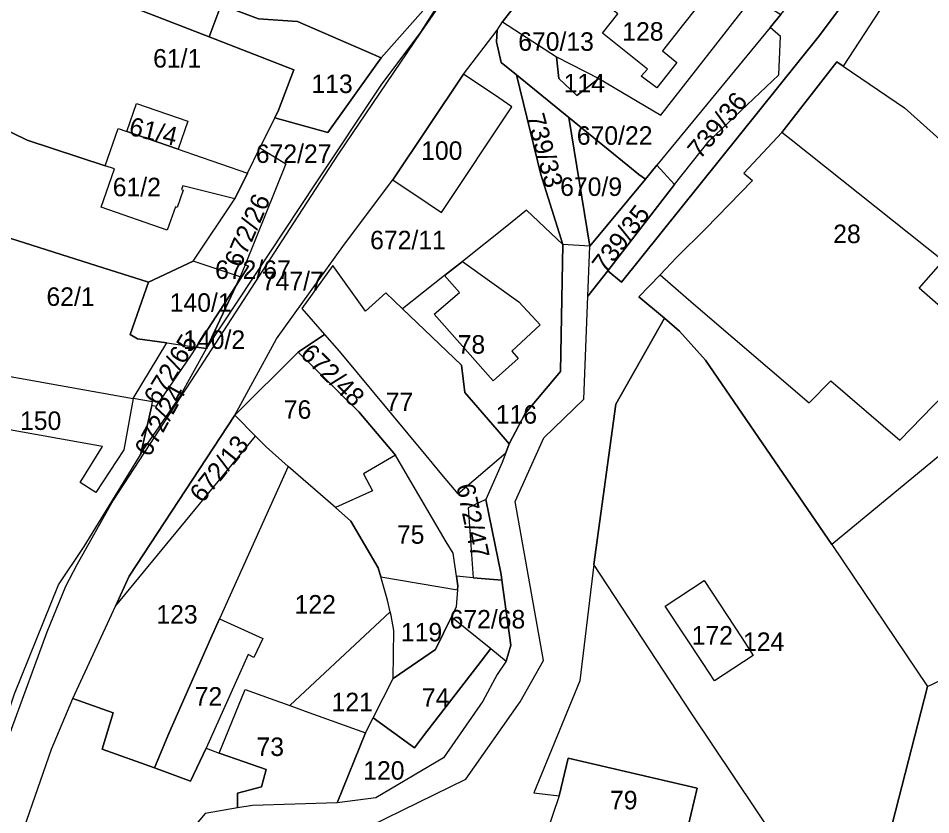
# Model space of a CAD drawing. Extents: x -629983 to -626385, y -1072828 to -1067897.
# Drawn here: x -627674 to -627526.1, y -1070665.2 to -1070536 of the extents above; entities that cross this region are included whole.
import ezdxf

# ---------------------------------------------------------------- set-up
doc = ezdxf.new("R2010")
doc.units = 0
doc.layers.add('Parcela nároku', color=7, linetype='Continuous')
doc.layers.add('Parcelní číslo', color=7, linetype='Continuous')

msp = doc.modelspace()

# ---------------------------------------------------------------- linework, layer by layer
at = {"layer": 'Parcela nároku'}
for points in [[(-627673.05, -1070667.34), (-627668.64, -1070654.56), (-627665.13, -1070646.37), (-627658.25, -1070631.4), (-627656.03, -1070626.54), (-627638.9, -1070600.43), (-627632.14, -1070588.03), (-627621.09, -1070572.65), (-627613.29, -1070562.25), (-627601.8, -1070545.09), (-627596.37, -1070537.95), (-627595.51, -1070536.64), (-627592.06, -1070532.18), (-627582.07, -1070517.94), (-627580.74, -1070516.18), (-627560.93, -1070497.47), (-627556.12, -1070493.99), (-627551.42, -1070491.21), (-627543.28, -1070485.96), (-627536.7, -1070481.88), (-627526.35, -1070474.99), (-627505.98, -1070464.68), (-627477.81, -1070449.31)], [(-627616.87, -1070667.02), (-627601.41, -1070659.46), (-627592.65, -1070646.92), (-627588.86, -1070640.21), (-627593.43, -1070614.39), (-627588.8, -1070604.09), (-627582.29, -1070597.82), (-627581.64, -1070581.12), (-627578.43, -1070576.98), (-627576.18, -1070578.86), (-627544.29, -1070539.1), (-627534.71, -1070526.26), (-627519.29, -1070510.38), (-627512.24, -1070505.66), (-627505.99, -1070502.74), (-627490.53, -1070498.43), (-627456.03, -1070492.74), (-627451.19, -1070491.95), (-627447.63, -1070491.37), (-627439.53, -1070490.04), (-627424.62, -1070486.69), (-627414.27, -1070478.04), (-627406.21, -1070468.57), (-627399.6, -1070453.47)], [(-627679.55, -1070528.79), (-627671.18, -1070532.92), (-627668.95, -1070530.68), (-627662.07, -1070534.21), (-627661.2, -1070531.98), (-627643.07, -1070539.03), (-627641.12, -1070533.86), (-627635.06, -1070536.12), (-627628.71, -1070536.58), (-627615.15, -1070542.47), (-627607.12, -1070533.38), (-627637.14, -1070522.87), (-627638.08, -1070527.06), (-627646.29, -1070525.29), (-627642.21, -1070504.86), (-627633.99, -1070506.92), (-627628.57, -1070508.55), (-627628.09, -1070506.86), (-627606.3, -1070513.99), (-627606.23, -1070513.77), (-627610.81, -1070511.8), (-627641.48, -1070502.11), (-627669.39, -1070497.42), (-627689.21, -1070528.16)], [(-627519.29, -1070510.38), (-627534.71, -1070526.26), (-627544.29, -1070539.1), (-627576.18, -1070578.86), (-627578.43, -1070576.98), (-627567.59, -1070562.99), (-627561.97, -1070555.94), (-627550.68, -1070545.19), (-627550.44, -1070538.98), (-627552.11, -1070537.56), (-627550.37, -1070535.44), (-627538.72, -1070521.1), (-627534.79, -1070517.05), (-627530.21, -1070512.83), (-627528.88, -1070511.61), (-627521.61, -1070505.05)], [(-627521.12, -1070517.11), (-627527.39, -1070524.31), (-627529.07, -1070526.23), (-627532.54, -1070531.92), (-627540.27, -1070543.83), (-627541.26, -1070543.12), (-627550.19, -1070554.58), (-627556.38, -1070561.14), (-627554.98, -1070562.37), (-627562.6, -1070570.16), (-627567.25, -1070574.84), (-627569.95, -1070577.66), (-627573.36, -1070581.22), (-627569.24, -1070584.65), (-627577.13, -1070598.62), (-627580.7, -1070624.63), (-627582.95, -1070643.48), (-627590.39, -1070661.64), (-627586.3, -1070662.14), (-627589.48, -1070671.55)], [(-627602.41, -1070529.11), (-627608.75, -1070538.3), (-627622.12, -1070558.08), (-627628.65, -1070568.14), (-627645.23, -1070593.66), (-627658.6, -1070614.18), (-627664.52, -1070624.66), (-627666.36, -1070628.21), (-627669.39, -1070635.62), (-627675.15, -1070651.38)], [(-627689.42, -1070689.81), (-627681.09, -1070664.8), (-627674.6, -1070645.58), (-627667.48, -1070627.92), (-627663.32, -1070621.69), (-627654.2, -1070606.83), (-627653.79, -1070606.16), (-627647.92, -1070597.59), (-627643.48, -1070589.58), (-627625.71, -1070562.74), (-627615.15, -1070546.88), (-627608.75, -1070538.3), (-627622.12, -1070558.08), (-627628.65, -1070568.14), (-627645.23, -1070593.66), (-627658.6, -1070614.18), (-627664.52, -1070624.66), (-627666.36, -1070628.21), (-627669.39, -1070635.62), (-627675.15, -1070651.38), (-627682.5, -1070674.74)], [(-627677.62, -1070571.01), (-627661.28, -1070576.19), (-627652.89, -1070578.85), (-627645.66, -1070575.41), (-627638.87, -1070565.34), (-627647.34, -1070563.2), (-627647.54, -1070563.8), (-627647.26, -1070563.9), (-627648.25, -1070566.73), (-627648.53, -1070566.63), (-627649.85, -1070570.41), (-627660.57, -1070566.67), (-627658.41, -1070560.48), (-627659.9, -1070559.99), (-627672.57, -1070555.81), (-627688.24, -1070548.18)], [(-627616.87, -1070667.02), (-627601.41, -1070659.46), (-627592.65, -1070646.92), (-627588.86, -1070640.21), (-627593.43, -1070614.39), (-627588.8, -1070604.09), (-627582.29, -1070597.82), (-627581.64, -1070581.12), (-627581.32, -1070573.01), (-627585.71, -1070572.7), (-627586.07, -1070593.35), (-627591.79, -1070600.14), (-627594.42, -1070605.04), (-627594.95, -1070606.49), (-627595.52, -1070608.06), (-627598.18, -1070614.09), (-627595.73, -1070626.23), (-627595.61, -1070627.14), (-627594.16, -1070637.72), (-627594.88, -1070640.29), (-627596.38, -1070642.48), (-627598.68, -1070646.78), (-627605.04, -1070655.97), (-627616.01, -1070662.49), (-627622.27, -1070663.25), (-627636.05, -1070663.69), (-627638.48, -1070664.1), (-627643.72, -1070664.99), (-627648.34, -1070670.51)], [(-627674.6, -1070645.58), (-627667.48, -1070627.92), (-627663.32, -1070621.69), (-627654.2, -1070606.83), (-627652.35, -1070598.82), (-627652.22, -1070598.24), (-627655.37, -1070597.68), (-627656.91, -1070606.05), (-627661.42, -1070612.95), (-627663.99, -1070611.33), (-627660.34, -1070605.48), (-627686.35, -1070600.86)]]:
    msp.add_lwpolyline(points, dxfattribs=at)
for points in [[(-627582.48, -1070503.53), (-627583.3, -1070504.47), (-627588.97, -1070511.44), (-627594.85, -1070518.68), (-627597.34, -1070521.75), (-627600.84, -1070525.92), (-627608.75, -1070538.3), (-627602.41, -1070529.11), (-627600.54, -1070526.75), (-627595.56, -1070520.84), (-627589.61, -1070514.26), (-627579.3, -1070504.8), (-627573.94, -1070500.28), (-627564.06, -1070492.76), (-627563.7, -1070492.26), (-627563.62, -1070491.72), (-627563.73, -1070491.09), (-627564.55, -1070487.72), (-627564.9, -1070486.29), (-627576.54, -1070496.78), (-627581.18, -1070502.06)], [(-627550.19, -1070554.58), (-627541.26, -1070543.12), (-627540.27, -1070543.83), (-627530.29, -1070550.54), (-627520.48, -1070559.4), (-627512.61, -1070563.45), (-627505.35, -1070549.36), (-627513.22, -1070545.31), (-627508.58, -1070536.93), (-627513.85, -1070533.39), (-627521.11, -1070528.52), (-627527.39, -1070524.31), (-627521.12, -1070517.11), (-627505.54, -1070534.77), (-627482.52, -1070560.73), (-627475.03, -1070556.53), (-627473.88, -1070560.2), (-627493.09, -1070564.88), (-627514.26, -1070577.27), (-627521.4, -1070577.52), (-627524.03, -1070575.35), (-627548.69, -1070555.77)], [(-627568.16, -1070523.81), (-627569.5, -1070523.01), (-627571.43, -1070523.34), (-627574.6, -1070524.75), (-627581.08, -1070528.36), (-627592.06, -1070532.18), (-627595.51, -1070536.64), (-627586.72, -1070542.29), (-627579.86, -1070545.8), (-627569.82, -1070551.77), (-627554.9, -1070532.59), (-627564.16, -1070526.72)], [(-627529.07, -1070526.23), (-627532.54, -1070531.92), (-627540.27, -1070543.83), (-627530.29, -1070550.54), (-627520.48, -1070559.4), (-627512.61, -1070563.45), (-627505.35, -1070549.36), (-627513.22, -1070545.31), (-627508.58, -1070536.93), (-627513.85, -1070533.39), (-627521.11, -1070528.52), (-627527.39, -1070524.31)], [(-627623.79, -1070554.58), (-627632.41, -1070552.2), (-627634.81, -1070557.07), (-627630.61, -1070559.65), (-627637.23, -1070576.04), (-627636.69, -1070576.22), (-627637.63, -1070577.77), (-627638.66, -1070579.37), (-627643.48, -1070589.58), (-627625.71, -1070562.74), (-627615.15, -1070546.88), (-627608.75, -1070538.3), (-627600.84, -1070525.92), (-627607.12, -1070533.38), (-627615.15, -1070542.47)], [(-627679.55, -1070528.79), (-627688.24, -1070548.18), (-627672.57, -1070555.81), (-627659.9, -1070559.99), (-627657.81, -1070553.92), (-627656.38, -1070554.41), (-627654.85, -1070549.86), (-627646.49, -1070552.75), (-627648.05, -1070557.27), (-627645.57, -1070558.14), (-627636.82, -1070561.16), (-627634.81, -1070557.07), (-627632.41, -1070552.2), (-627631.8, -1070550.95), (-627629.3, -1070544.38), (-627643.07, -1070539.03), (-627661.2, -1070531.98), (-627662.07, -1070534.21), (-627668.95, -1070530.68), (-627671.18, -1070532.92)], [(-627575.98, -1070532.62), (-627574.27, -1070530.47), (-627573.41, -1070531.16), (-627571.3, -1070528.5), (-627564.02, -1070534.33), (-627566.12, -1070536.99), (-627569.55, -1070541.31), (-627567.24, -1070543.2), (-627570.47, -1070547.33), (-627572.98, -1070545.4), (-627571.98, -1070544.27), (-627579.28, -1070538.47), (-627576.8, -1070535.34), (-627578.17, -1070534.26), (-627576.52, -1070532.19)], [(-627570.47, -1070547.33), (-627572.98, -1070545.4), (-627571.98, -1070544.27), (-627579.28, -1070538.47), (-627576.8, -1070535.34), (-627578.17, -1070534.26), (-627576.52, -1070532.19), (-627575.98, -1070532.62), (-627574.27, -1070530.47), (-627573.41, -1070531.16), (-627571.3, -1070528.5), (-627564.02, -1070534.33), (-627566.12, -1070536.99), (-627569.55, -1070541.31), (-627567.24, -1070543.2)], [(-627583.45, -1070548.54), (-627579.86, -1070545.8), (-627569.82, -1070551.77), (-627554.9, -1070532.59), (-627551.93, -1070534.47), (-627550.37, -1070535.44), (-627552.11, -1070537.56), (-627570.45, -1070559.87), (-627572.32, -1070562.15), (-627573.39, -1070561.35), (-627575.16, -1070559.92), (-627584.73, -1070552.13), (-627593.22, -1070545.23), (-627595.7, -1070543.21), (-627596.46, -1070539.84), (-627596.37, -1070537.95), (-627595.51, -1070536.64), (-627586.72, -1070542.29), (-627586.38, -1070545.8)], [(-627615.15, -1070542.47), (-627628.71, -1070536.58), (-627635.06, -1070536.12), (-627641.12, -1070533.86), (-627643.07, -1070539.03), (-627629.3, -1070544.38), (-627631.8, -1070550.95), (-627632.41, -1070552.2), (-627623.79, -1070554.58)], [(-627607.55, -1070566.09), (-627605.37, -1070567.54), (-627593.95, -1070550.39), (-627596.06, -1070548.93), (-627601.8, -1070545.09), (-627596.37, -1070537.95), (-627596.46, -1070539.84), (-627595.7, -1070543.21), (-627593.22, -1070545.23), (-627589.28, -1070561.39), (-627585.71, -1070572.7), (-627591.58, -1070567.16), (-627594.79, -1070569.76), (-627601.99, -1070575.46), (-627604.88, -1070577.75), (-627611.69, -1070583.15), (-627614.39, -1070580.56), (-627617.72, -1070583.52), (-627622.99, -1070576.15), (-627628.05, -1070583.11), (-627624.37, -1070587.32), (-627628.61, -1070590.21), (-627638.9, -1070600.43), (-627632.14, -1070588.03), (-627621.09, -1070572.65), (-627613.29, -1070562.25)], [(-627550.44, -1070538.98), (-627552.11, -1070537.56), (-627570.45, -1070559.87), (-627567.59, -1070562.99), (-627561.97, -1070555.94), (-627550.68, -1070545.19)], [(-627586.72, -1070542.29), (-627579.86, -1070545.8), (-627583.45, -1070548.54), (-627586.38, -1070545.8)], [(-627596.06, -1070548.93), (-627601.8, -1070545.09), (-627613.29, -1070562.25), (-627607.55, -1070566.09), (-627605.37, -1070567.54), (-627593.95, -1070550.39)], [(-627584.73, -1070552.13), (-627581.32, -1070573.01), (-627585.71, -1070572.7), (-627589.28, -1070561.39), (-627593.22, -1070545.23)], [(-627654.85, -1070549.86), (-627646.49, -1070552.75), (-627648.05, -1070557.27), (-627656.38, -1070554.41)], [(-627584.73, -1070552.13), (-627575.16, -1070559.92), (-627573.39, -1070561.35), (-627572.32, -1070562.15), (-627581.32, -1070573.01)], [(-627645.57, -1070558.14), (-627636.82, -1070561.16), (-627638.87, -1070565.34), (-627647.34, -1070563.2), (-627647.54, -1070563.8), (-627647.26, -1070563.9), (-627648.25, -1070566.73), (-627648.53, -1070566.63), (-627649.85, -1070570.41), (-627660.57, -1070566.67), (-627658.41, -1070560.48), (-627659.9, -1070559.99), (-627657.81, -1070553.92), (-627656.38, -1070554.41), (-627648.05, -1070557.27)], [(-627548.69, -1070555.77), (-627550.19, -1070554.58), (-627556.38, -1070561.14), (-627554.98, -1070562.37), (-627562.6, -1070570.16), (-627567.25, -1070574.84), (-627569.95, -1070577.66), (-627564.5, -1070582.33), (-627545.76, -1070598.4), (-627542.27, -1070594.84), (-627531.04, -1070604.44), (-627516.67, -1070589.65), (-627527.92, -1070579.8), (-627524.03, -1070575.35)], [(-627634.81, -1070557.07), (-627630.61, -1070559.65), (-627637.23, -1070576.04), (-627638, -1070577.96), (-627645.66, -1070575.41), (-627638.87, -1070565.34), (-627636.82, -1070561.16)], [(-627581.32, -1070573.01), (-627572.32, -1070562.15), (-627570.45, -1070559.87), (-627567.59, -1070562.99), (-627578.43, -1070576.98), (-627581.64, -1070581.12)], [(-627493.09, -1070564.88), (-627473.88, -1070560.2), (-627468.28, -1070573), (-627513.68, -1070597.9), (-627542.07, -1070621.38), (-627562.59, -1070591.47), (-627566.78, -1070586.78), (-627569.24, -1070584.65), (-627573.36, -1070581.22), (-627569.95, -1070577.66), (-627564.5, -1070582.33), (-627545.76, -1070598.4), (-627542.27, -1070594.84), (-627531.04, -1070604.44), (-627516.67, -1070589.65), (-627527.92, -1070579.8), (-627524.03, -1070575.35), (-627521.4, -1070577.52), (-627514.26, -1070577.27)], [(-627594.79, -1070569.76), (-627601.99, -1070575.46), (-627592.86, -1070582.05), (-627589.36, -1070585.78), (-627593.99, -1070590.04), (-627592.94, -1070591.22), (-627596.99, -1070594.82), (-627606.59, -1070584.01), (-627602.44, -1070580.5), (-627604.88, -1070577.75), (-627611.69, -1070583.15), (-627602.13, -1070592.32), (-627601.61, -1070596.73), (-627596.38, -1070602.77), (-627594.42, -1070605.04), (-627591.79, -1070600.14), (-627586.07, -1070593.35), (-627585.71, -1070572.7), (-627591.58, -1070567.16)], [(-627694.01, -1070569.01), (-627688.94, -1070569.9), (-627688.67, -1070568.31), (-627680.79, -1070569.36), (-627682.19, -1070577.99), (-627684.57, -1070592.5), (-627684.12, -1070592.58), (-627655.37, -1070597.68), (-627656.91, -1070606.05), (-627661.42, -1070612.95), (-627663.99, -1070611.33), (-627660.34, -1070605.48), (-627686.35, -1070600.86), (-627685.99, -1070598.91), (-627696.8, -1070597.09), (-627693.25, -1070576.16), (-627698.67, -1070575.26), (-627697.8, -1070570.04), (-627694.32, -1070570.65)], [(-627661.28, -1070576.19), (-627677.62, -1070571.01), (-627679.57, -1070577.47), (-627684.12, -1070592.58), (-627655.37, -1070597.68), (-627649.93, -1070588.69), (-627654.69, -1070588.03), (-627655.85, -1070587.31), (-627652.89, -1070578.85)], [(-627467.55, -1070574.63), (-627468.28, -1070573), (-627513.68, -1070597.9), (-627542.07, -1070621.38), (-627526.57, -1070644.43), (-627524.44, -1070643.36), (-627497.28, -1070630.97), (-627469.47, -1070618.25), (-627449.08, -1070608.65)], [(-627638, -1070577.96), (-627645.66, -1070575.41), (-627652.89, -1070578.85), (-627655.85, -1070587.31), (-627654.69, -1070588.03), (-627649.93, -1070588.69), (-627645.14, -1070589.35), (-627638.66, -1070579.37)], [(-627638, -1070577.96), (-627638.66, -1070579.37), (-627637.63, -1070577.77), (-627636.69, -1070576.22), (-627637.23, -1070576.04)], [(-627617.72, -1070583.52), (-627622.99, -1070576.15), (-627628.05, -1070583.11), (-627624.37, -1070587.32), (-627621.99, -1070590.04), (-627607.9, -1070606.97), (-627605.09, -1070610.34), (-627602.72, -1070613.18), (-627594.95, -1070606.49), (-627594.42, -1070605.04), (-627596.38, -1070602.77), (-627601.61, -1070596.73), (-627602.13, -1070592.32), (-627611.69, -1070583.15), (-627614.39, -1070580.56)], [(-627601.99, -1070575.46), (-627592.86, -1070582.05), (-627589.36, -1070585.78), (-627593.99, -1070590.04), (-627592.94, -1070591.22), (-627596.99, -1070594.82), (-627606.59, -1070584.01), (-627602.44, -1070580.5), (-627604.88, -1070577.75)], [(-627638.66, -1070579.37), (-627645.14, -1070589.35), (-627643.48, -1070589.58)], [(-627542.07, -1070621.38), (-627526.57, -1070644.43), (-627538.48, -1070690.73), (-627541.71, -1070690.64), (-627540.39, -1070685.21), (-627564.91, -1070648.66), (-627580.7, -1070624.63), (-627577.13, -1070598.62), (-627569.24, -1070584.65), (-627566.78, -1070586.78), (-627562.59, -1070591.47)], [(-627628.61, -1070590.21), (-627624.37, -1070587.32), (-627621.99, -1070590.04), (-627607.9, -1070606.97), (-627605.09, -1070610.34), (-627602.72, -1070613.18), (-627594.95, -1070606.49), (-627595.52, -1070608.06), (-627598.18, -1070614.09), (-627601.04, -1070615.44), (-627600.27, -1070626.76), (-627602.94, -1070626.54), (-627603.48, -1070622.76), (-627604.62, -1070620.94), (-627611.27, -1070609.59), (-627612.86, -1070606.87), (-627618.8, -1070599.86)], [(-627655.37, -1070597.68), (-627649.93, -1070588.69), (-627645.14, -1070589.35), (-627646.06, -1070590.77), (-627651.7, -1070598.99), (-627652.35, -1070598.82), (-627652.22, -1070598.24)], [(-627652.35, -1070598.82), (-627654.2, -1070606.83), (-627653.79, -1070606.16), (-627647.92, -1070597.59), (-627643.48, -1070589.58), (-627645.14, -1070589.35), (-627646.06, -1070590.77), (-627651.7, -1070598.99)], [(-627638.9, -1070600.43), (-627628.61, -1070590.21), (-627618.8, -1070599.86), (-627612.86, -1070606.87), (-627618.05, -1070609.91), (-627616.58, -1070612.7), (-627622.56, -1070615.38), (-627630.22, -1070608.71), (-627633.83, -1070605.54), (-627635.55, -1070603.8)], [(-627638.9, -1070600.43), (-627656.03, -1070626.54), (-627658.25, -1070631.4), (-627635.55, -1070603.8)], [(-627633.83, -1070605.54), (-627630.22, -1070608.71), (-627641.36, -1070633.42), (-627642.77, -1070636.55), (-627649.59, -1070652.03), (-627651.93, -1070657.59), (-627660.41, -1070654.55), (-627658.61, -1070648.69), (-627665.13, -1070646.37), (-627658.25, -1070631.4), (-627635.55, -1070603.8)], [(-627603.48, -1070622.76), (-627604.62, -1070620.94), (-627611.27, -1070609.59), (-627612.86, -1070606.87), (-627618.05, -1070609.91), (-627616.58, -1070612.7), (-627622.56, -1070615.38), (-627620.06, -1070617.59), (-627615.66, -1070625.19), (-627615.23, -1070626.64), (-627602.77, -1070628.74), (-627602.72, -1070628.09), (-627602.94, -1070626.54)], [(-627615.23, -1070626.64), (-627615.66, -1070625.19), (-627620.06, -1070617.59), (-627622.56, -1070615.38), (-627630.22, -1070608.71), (-627641.36, -1070633.42), (-627634.35, -1070636.62), (-627635.81, -1070639.72), (-627636.74, -1070639.24), (-627643.55, -1070654.42), (-627641.41, -1070655.21), (-627637.19, -1070644.88), (-627633.16, -1070646.34), (-627629.96, -1070647.5), (-627613.69, -1070632.29), (-627614.11, -1070630.43)], [(-627595.61, -1070627.14), (-627595.73, -1070626.23), (-627598.18, -1070614.09), (-627601.04, -1070615.44), (-627600.27, -1070626.76), (-627598.94, -1070626.87)], [(-627589.48, -1070671.55), (-627595.46, -1070670.93), (-627598.44, -1070677.62), (-627592.88, -1070680.57), (-627571.53, -1070692.59), (-627569.47, -1070689.06), (-627541.71, -1070690.64), (-627540.39, -1070685.21), (-627564.91, -1070648.66), (-627580.7, -1070624.63), (-627582.95, -1070643.48), (-627590.39, -1070661.64), (-627586.3, -1070662.14), (-627584.83, -1070656.02), (-627563.92, -1070660.92), (-627565.36, -1070667.05), (-627565.86, -1070669.19), (-627558.55, -1070670.9), (-627561.94, -1070685.4), (-627569.25, -1070683.69), (-627578.88, -1070682.79), (-627591.75, -1070678.7), (-627590.9, -1070676.02)], [(-627615.23, -1070626.64), (-627602.77, -1070628.74), (-627602.98, -1070631.49), (-627603.78, -1070633.12), (-627606.37, -1070638.41), (-627613.24, -1070643.12), (-627613.1, -1070635.35), (-627613.55, -1070632.9), (-627613.69, -1070632.29), (-627614.11, -1070630.43)], [(-627594.16, -1070637.72), (-627595.61, -1070627.14), (-627598.94, -1070626.87), (-627600.27, -1070626.76), (-627602.94, -1070626.54), (-627602.72, -1070628.09), (-627602.77, -1070628.74), (-627602.98, -1070631.49), (-627603.78, -1070633.12), (-627597.36, -1070638.24), (-627594.88, -1070640.29)], [(-627562.97, -1070640.66), (-627569.09, -1070631.36), (-627562.81, -1070627.23), (-627556.71, -1070636.54), (-627554.86, -1070639.37), (-627561.12, -1070643.5)], [(-627569.09, -1070631.36), (-627562.81, -1070627.23), (-627556.71, -1070636.54), (-627554.86, -1070639.37), (-627561.12, -1070643.5), (-627562.97, -1070640.66)], [(-627613.55, -1070632.9), (-627613.69, -1070632.29), (-627629.96, -1070647.5), (-627627.49, -1070648.4), (-627617.71, -1070651.95), (-627616.46, -1070649.48), (-627613.24, -1070643.12), (-627613.1, -1070635.35)], [(-627642.77, -1070636.55), (-627641.36, -1070633.42), (-627634.35, -1070636.62), (-627635.81, -1070639.72), (-627636.74, -1070639.24), (-627643.55, -1070654.42), (-627646.07, -1070659.74), (-627651.93, -1070657.59), (-627649.59, -1070652.03)], [(-627603.78, -1070633.12), (-627597.36, -1070638.24), (-627598.95, -1070640.31), (-627608.29, -1070652.41), (-627609.76, -1070654.34), (-627616.46, -1070649.48), (-627613.24, -1070643.12), (-627606.37, -1070638.41)], [(-627608.29, -1070652.41), (-627598.95, -1070640.31), (-627597.36, -1070638.24), (-627594.88, -1070640.29), (-627596.38, -1070642.48), (-627598.68, -1070646.78), (-627605.04, -1070655.97), (-627616.01, -1070662.49), (-627622.27, -1070663.25), (-627617.71, -1070651.95), (-627616.46, -1070649.48), (-627609.76, -1070654.34)], [(-627526.57, -1070644.43), (-627524.44, -1070643.36), (-627494.54, -1070708.53), (-627485.16, -1070729.61), (-627467.69, -1070772.62), (-627459.42, -1070795.95), (-627450.33, -1070820.66), (-627444.51, -1070837.95), (-627440.33, -1070852.16), (-627482.19, -1070847.21), (-627487.27, -1070833.79), (-627496.33, -1070806.96), (-627518.25, -1070750.64), (-627541.19, -1070696.77), (-627538.48, -1070690.73)], [(-627633.16, -1070646.34), (-627629.96, -1070647.5), (-627627.49, -1070648.4), (-627617.71, -1070651.95), (-627622.27, -1070663.25), (-627636.05, -1070663.69), (-627638.48, -1070664.1), (-627638.43, -1070661.72), (-627634.57, -1070660.67), (-627633.82, -1070657.85), (-627637.37, -1070656.62), (-627641.41, -1070655.21), (-627637.19, -1070644.88)], [(-627660.41, -1070654.55), (-627651.93, -1070657.59), (-627646.07, -1070659.74), (-627643.55, -1070654.42), (-627641.41, -1070655.21), (-627637.37, -1070656.62), (-627633.82, -1070657.85), (-627634.57, -1070660.67), (-627638.43, -1070661.72), (-627638.48, -1070664.1), (-627643.72, -1070664.99), (-627648.34, -1070670.51), (-627649.88, -1070673.63), (-627649.95, -1070674.04), (-627650.67, -1070678.07), (-627657.63, -1070678.84), (-627675.56, -1070679.12), (-627678.18, -1070679.19), (-627673.05, -1070667.34), (-627668.64, -1070654.56), (-627665.13, -1070646.37), (-627658.61, -1070648.69)], [(-627589.48, -1070671.55), (-627590.9, -1070676.02), (-627591.75, -1070678.7), (-627578.88, -1070682.79), (-627569.25, -1070683.69), (-627561.94, -1070685.4), (-627558.55, -1070670.9), (-627565.86, -1070669.19), (-627565.36, -1070667.05), (-627563.92, -1070660.92), (-627584.83, -1070656.02), (-627586.3, -1070662.14)]]:
    msp.add_lwpolyline(points, close=True, dxfattribs=at)

# ---------------------------------------------------------------- texts
at = {"layer": 'Parcelní číslo'}
for s, p in [('128', (-627576.07, -1070539.67)), ('670/13', (-627592.94, -1070541.31)), ('61/1', (-627652.14, -1070544.03)), ('113', (-627626.47, -1070548.16)), ('114', (-627585.57, -1070548.05)), ('670/22', (-627583.44, -1070556.55)), ('672/27', (-627635.49, -1070559.5)), ('100', (-627608.68, -1070559)), ('61/2', (-627658.68, -1070564.9)), ('670/9', (-627586.14, -1070564.85)), ('672/11', (-627616.95, -1070573.5)), ('28', (-627541.87, -1070572.5)), ('672/67', (-627642.09, -1070578.31)), ('747/7', (-627634.51, -1070580.15)), ('62/1', (-627669.43, -1070582.68)), ('140/1', (-627649.45, -1070583.64)), ('140/2', (-627647.26, -1070589.66)), ('78', (-627602.76, -1070590.43)), ('77', (-627614.42, -1070599.73)), ('76', (-627630.95, -1070600.99)), ('116', (-627596.58, -1070601.78)), ('150', (-627673.72, -1070602.8)), ('75', (-627612.61, -1070621.26)), ('122', (-627629.2, -1070632.58)), ('123', (-627651.61, -1070634.21)), ('672/68', (-627604.07, -1070635)), ('119', (-627611.96, -1070637.1)), ('172', (-627564.82, -1070637.61)), ('124', (-627556.49, -1070638.64)), ('72', (-627645.4, -1070647.51)), ('121', (-627623.2, -1070648.42)), ('74', (-627608.56, -1070647.7)), ('73', (-627635.38, -1070655.68)), ('120', (-627618.07, -1070659.52)), ('79', (-627578.06, -1070664.33))]:
    msp.add_text(s, height=3, dxfattribs=at).set_placement(p)
for s, rotation, p in [('739/36', 50.125, (-627563.46, -1070559.03)), ('739/33', 285.2054, (-627591.7, -1070551.93)), ('61/4', 346.5042, (-627656.23, -1070554.92)), ('672/26', 66.5139, (-627637.96, -1070576.63)), ('739/35', 52.9132, (-627578.83, -1070577.58)), ('672/65', 58.339, (-627651.3, -1070598.97)), ('672/48', 315.8032, (-627628.46, -1070590.69)), ('672/24', 61.1816, (-627652.7, -1070607.34)), ('672/13', 51.2157, (-627644.12, -1070614.8)), ('672/47', 281.9377, (-627603.01, -1070611.84))]:
    msp.add_text(s, height=3, rotation=rotation, dxfattribs=at).set_placement(p)

doc.saveas('drawing.dxf')
